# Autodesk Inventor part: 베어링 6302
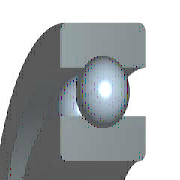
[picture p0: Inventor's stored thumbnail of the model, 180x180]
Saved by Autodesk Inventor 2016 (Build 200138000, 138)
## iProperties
IsCustomPart: 1
Created: 2012-02
Part Number: 베어링 6302
Material: 강철, 연강
Document SubType Name: Modeling
Standard: JIS B 1521
Designer: mdu-01
Standards Organization: JIS
Language: ko-KR
Size Designation: 6302 15x42x13
Categories: <MemberInstance><Categories><Category DisplayName="샤프트 부품" InternalName="7f7aeb1f-a693-4053-b835-cee3144e0d98" Mnemonic="SHFT"><Category DisplayName="베어링" Inter
Density: 1 g/cm^3
Appearance: 노란색
Author: mdu-01
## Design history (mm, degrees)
sketch "스케치" dims "d0" = 7.02 (= -0.26 x WD + 0.26 x BD)
  geometry: L1 (2.99, 14.25)-(10.01, 14.25); L2 (6.5, 14.25)-(6.5, 10.74); L3 (6.5, 14.25)-(6.5, 17.76); L4 (3.892, 11.901)-(0, 11.901); L5 (0, 7.5)-(13, 7.5); L6 (3.892, 16.599)-(0, 16.599); L7 (0, 21)-(13, 21); L8 (13, 7.5)-(13, 11.901); L9 (9.108, 11.901)-(13, 11.901); L10 (9.108, 16.599)-(13, 16.599); L11 (13, 21)-(13, 16.599); L12 (-1.4, 0)-(8.4, 0) reference; L13 (0, -0.3)-(0, 5.3) reference
  constraints: 22 end point, 4 point on line, 2 collinear, 2 perpendicular, 2 symmetric about line, 1 midpoint, 1 parallel, 14 other
  dimensions: "d9" = 15 diameter of L5 L12 (= WD); "d11" = 42 diameter of L7 L12 (= BD); "d12" = 13 distance between parallel lines of L8 L13 (= KB); "d13" = 23.802 diameter of L9 L12 (= 0.326 x BD + 0.674 x WD)
revolve "본체" stored, may be unused: angle "d6" = 90 deg
revolve "볼" stored, may be unused: angle "d7" = 90 deg
pattern_circular "IDS_ARRAYBALL[SIMPL:T]" dims angle "d3" = 360 deg
body "Solid1"
fillet "모깎기1" dims "d1" = 1 (= KRS)
other parameters: "WD" = 15 [user parameter; used in 5 equation terms], "BD" = 42 [user parameter; used in 5 equation terms], "KB" = 13 [user parameter; used in 1 equation term], "KRS" = 1 [user parameter; used in 1 equation term], "d4" = 0, "d5" = 0, "d8" = 0, "d14" = 0, "d15" = 0, "BBA" = 0 [user parameter], "BC0" = 5400000 [user parameter], "BC" = 1.14e+07 [user parameter], "BR" = 21 (= 0.5 x BD) [user parameter], "WR" = 7.5 (= 0.5 x WD) [user parameter]
